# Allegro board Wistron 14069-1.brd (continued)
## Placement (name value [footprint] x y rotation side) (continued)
R1619  10KR2J-3-GP  [R402H16]  170.02 54.83 90 top
R1620  10KR2J-3-GP  [R402H16]  168.81 50.16 90 top
R1621  10KR2J-3-GP  [R402H16]  170.94 48.56 90 top
R1622  10KR2J-3-GP  [R402H16]  172.01 46.46 270 top
R1701  0R2J-2-GP  [R402H16]  130.16 43.31 90 top
R1703  0R0402-PAD-2-GP  [0R0402-PAD-1]  180.52 39.75 90 top
R1704  560R2J-3-GP  [R402H16]  130.86 45.82 270 top
R1705  30R2J-1-GP  [R402H16]  130.84 44.73 270 top
R1706  1KR2J-1-GP  [R402H16]  132.56 42.94 0 top
R1707  1KR2J-1-GP  [R402H16]  124.53 41.22 270 top
R1708  0R2J-2-GP  [R402H16]  221.79 9.73 270 top
R1709  0R2J-2-GP  [R402H16]  196.63 27.64 270 top
R1710  0R2J-2-GP  [R402H16]  196.63 28.79 270 top
R1711  0R2J-2-GP  [R402H16]  221.82 8.64 270 top
R1801  0R0402-PAD-2-GP  [0R0402-PAD-1]  177.23 30.65 270 top
R1803  2K7R2F-GP  [R402H16]  138.13 57.98 0 top
R1807  1MR2J-1-GP  [R402H16]  138.13 60.25 0 top
R1808  10MR3J-L1-GP  [R603H22]  146.25 33.32 90 top
R1809  10KR2J-3-GP  [R402H16]  153.56 31.63 0 top
R1810  10KR2J-3-GP  [R402H16]  165.97 28.66 0 top
R1811  10KR2J-3-GP  [R402H16]  154.66 31.61 0 top
R1812  10KR2J-3-GP  [R402H16]  178.74 31.09 180 top
R1814  10KR2J-3-GP  [R402H16]  152.54 31.78 0 top
R1815  10KR2J-3-GP  [R402H16]  167 28.66 0 top
R1901  10KR2J-3-GP  [R402H16]  152.04 26.08 90 top
R1902  10KR2J-3-GP  [R402H16]  148.98 28.98 0 top
R1905  10KR2J-3-GP  [R402H16]  152.37 27.56 0 top
R1907  10KR2J-3-GP  [R402H16]  147.96 29.53 0 top
R1908  10KR2J-3-GP  [R402H16]  134.77 27.15 0 top
R1909  22R2J-2-GP  [R402H16]  162.56 24.36 0 top
R1910  22R2J-2-GP  [R402H16]  164.03 24.09 90 top
R1911  22R2J-2-GP  [R402H16]  161.52 24.36 0 top
R2002  1KR2F-3-GP  [R402H16]  170.3 37.49 90 top
R2003  1KR2F-3-GP  [R402H16]  170.25 38.54 90 top
R2004  1KR2F-3-GP  [R402H16]  176.75 36.23 180 top
R2005  1KR2F-3-GP  [R402H16]  176.79 32.65 180 top
R2006  75R3J-L-GP  [R603H22]  238.27 106.75 180 top
R2007  0R0402-PAD-2-GP  [0R0402-PAD-1]  149.91 23.91 90 top
R2008  2K2R2J-2-GP  [R402H16]  236.66 100.3 0 top
R2009  75R3J-L-GP  [R603H22]  237.03 106.75 180 top
R2010  1KR2J-1-GP  [R402H16]  238.13 100.72 90 top
R2011  10KR2J-3-GP  [R402H16]  132.81 32.19 180 top
R2012  0R2J-2-GP  [R402H16]  128.96 33.91 90 top
R2014  0R0402-PAD-2-GP  [0R0402-PAD-1]  127.99 28.35 270 top
R2015  2K2R2J-2-GP  [R402H16]  132.35 33.75 90 top
R2016  499R2F-2-GP  [R402H16]  166.73 37.71 90 top
R2017  33R2J-2-GP  [R402H16]  140.87 33.42 180 top
R2018  499R2F-2-GP  [R402H16]  167.45 35.23 90 top
R2019  1KR2J-1-GP  [R402H16]  166.69 40.13 90 top
R2020  33R2J-2-GP  [R402H16]  136.19 37.63 90 top
R2021  1KR2J-1-GP  [R402H16]  168.24 30.63 90 top
R2022  33R2J-2-GP  [R402H16]  139.41 33.86 90 top
R2023  10KR2J-3-GP  [R402H16]  158.97 29.53 0 top
R2024  8K2R2J-3-GP  [R402H16]  157.51 29.76 90 top
R2025  33R2J-2-GP  [R402H16]  136.73 32.77 270 top
R2026  10KR2J-3-GP  [R402H16]  146.36 42.48 90 bottom
R2027  10KR2J-3-GP  [R402H16]  130.05 27.84 0 top
R2028  33R2J-2-GP  [R402H16]  130.18 41.02 90 top
R2029  33R2J-2-GP  [R402H16]  130.17 39.99 90 top
R2030  1KR2J-1-GP  [R402H16]  149.17 27.09 0 top
R2031  100KR2J-1-GP  [R402H16]  131.09 28.83 0 top
R2032  10KR2J-3-GP  [R402H16]  150.21 26.55 0 top
R2034  10KR2J-3-GP  [R402H16]  149.11 31.95 0 top
R2035  1KR2J-1-GP  [R402H16]  124.54 36.8 270 top
R2036  0R2J-2-GP  [R402H16]  127.03 36.16 90 top
R2037  51D1R2F-GP  [R402H16]  130.54 38.39 270 top
R2038  51R2F-2-GP  [R402H16]  124.49 40.18 270 top
R2040  51R2F-2-GP  [R402H16]  124.48 39.12 270 top
R2043  51R2F-2-GP  [R402H16]  124.54 37.94 270 top
R2045  10KR2J-3-GP  [R402H16]  156.1 26.76 0 top
R2046  20KR2J-L2-GP  [R402H16]  143.18 25.28 90 top
R2047  10KR2J-3-GP  [R402H16]  148.11 26.97 0 top
R2048  1KR2J-1-GP  [R402H16]  154.06 28.92 0 top
R2049  20KR2J-L2-GP  [R402H16]  182.68 8.48 270 top
R2053  470R2F-GP  [R402H16]  152.26 23.45 180 top
R2054  4K7R2J-2-GP  [R402H16]  182.45 5.82 90 top
R2056  20KR2F-L-GP  [R402H16]  196.09 13.7 270 top
R2057  0R0402-PAD-2-GP  [0R0402-PAD-1]  196.1 12.61 90 top
R2058  1KR2J-1-GP  [R402H16]  195.53 14.98 270 top
R2059  1KR2J-1-GP  [R402H16]  195.88 21.51 0 top
R2060  0R0402-PAD-2-GP  [0R0402-PAD-1]  194.84 21.51 0 top
R2066  10KR2J-3-GP  [R402H16]  154.57 26.15 90 top
R2067  0R0402-PAD-2-GP  [0R0402-PAD-1]  130.68 31.11 180 top
R2101  0R2J-2-GP  [R402H16]  155.17 28.92 180 top
R2102  0R0603-PAD-2-GP-U  [0R0603-PAD-1-U]  162.31 27.69 0 top
R2104  0R0603-PAD-2-GP-U  [0R0603-PAD-1-U]  152.6 44.35 270 bottom
R2105  0R0603-PAD-2-GP-U  [0R0603-PAD-1-U]  135.71 35.53 270 top
R2106  30R2J-1-GP  [R402H16]  135.18 41.6 270 top
R2107  0R0402-PAD-2-GP  [0R0402-PAD-1]  142.9 50.38 270 bottom
R2108  0R0603-PAD-2-GP-U  [0R0603-PAD-1-U]  142.75 32.89 90 top
R2109  0R0603-PAD-2-GP-U  [0R0603-PAD-1-U]  165.14 36.75 270 bottom
R2110  0R0402-PAD-2-GP  [0R0402-PAD-1]  140.19 50.38 90 bottom
R2129  0R0603-PAD-2-GP-U  [0R0603-PAD-1-U]  167.08 36.53 270 top
R2130  30R2J-1-GP  [R402H16]  132.06 41.32 270 top
R2201  10KR2J-3-GP  [R402H16]  167.66 48.19 270 top
R2202  1KR2J-1-GP  [R402H16]  164.03 31.69 270 top
R2203  4K7R2J-2-GP  [R402H16]  162.15 31.53 90 top
R2204  20KR2J-L2-GP  [R402H16]  164.04 32.78 270 top
R2205  4K7R2J-2-GP  [R402H16]  162.15 32.62 90 top
R2206  20KR2J-L2-GP  [R402H16]  164.05 30.61 270 top
R2207  4K7R2J-2-GP  [R402H16]  162.15 30.46 90 top
R2208  20KR2J-L2-GP  [R402H16]  164.04 33.86 270 top
R2209  1KR2J-1-GP  [R402H16]  162.16 33.7 90 top
R2210  4K7R2J-2-GP  [R402H16]  158.77 32.59 270 top
R2211  20KR2J-L2-GP  [R402H16]  156.89 32.59 90 top
R2212  4K7R2J-2-GP  [R402H16]  158.76 33.72 270 top
R2213  1KR2J-1-GP  [R402H16]  156.88 33.72 90 top
R2214  4K7R2J-2-GP  [R402H16]  170.96 27.75 180 top
R2215  20KR2J-L2-GP  [R402H16]  170.53 29.73 270 top
R2217  4K7R2J-2-GP  [R402H16]  164.6 28.08 180 top
R2218  20KR2J-L2-GP  [R402H16]  163.51 28.08 180 top
R2219  4K7R2J-2-GP  [R402H16]  168.27 27.45 180 top
R2220  20KR2J-L2-GP  [R402H16]  169.33 27.44 180 top
R2221  4K7R2J-2-GP  [R402H16]  160.04 28.03 180 top
R2222  20KR2J-L2-GP  [R402H16]  161.09 28.08 180 top
R2223  4K7R2J-2-GP  [R402H16]  169.99 34.65 0 top
R2224  20KR2J-L2-GP  [R402H16]  168.91 34.65 0 top
R2225  10KR2J-3-GP  [R402H16]  167.68 47.13 270 top
R2227  1K5R2J-3-GP  [R402H16]  135.18 42.62 90 top
R2301  0R0603-PAD-2-GP-U  [0R0603-PAD-1-U]  145.42 52.38 90 bottom
R2302  0R0603-PAD-2-GP-U  [0R0603-PAD-1-U]  170.81 63.37 270 top
R2303  0R0603-PAD-2-GP-U  [0R0603-PAD-1-U]  149.82 44.5 90 bottom
R2304  0R0603-PAD-2-GP-U  [0R0603-PAD-1-U]  159.25 23.51 270 top
R2406  0R0603-PAD-2-GP-U  [0R0603-PAD-1-U]  20.45 76.58 270 top
R2475  43D2R2F-GP  [R402H16]  210.97 64.81 0 top
R2476  0R2J-2-GP  [R402H16]  207.7 62.89 90 top
R2477  0R2J-2-GP  [R402H16]  208.46 63.94 90 top
R2478  0R2J-2-GP  [R402H16]  226.8 75.36 0 top
R2479  1KR2J-1-GP  [R402H16]  213.36 52.94 0 top
R2480  0R0402-PAD-2-GP  [0R0402-PAD-1]  237.08 40.18 0 top
R2502  1KR2J-1-GP  [R402H16]  175.06 24.23 90 top
R2503  1KR2J-1-GP  [R402H16]  188.92 25.92 270 top
R2504  1KR2J-1-GP  [R402H16]  173.99 12.57 90 top
R2505  15R2F-2-GP  [R402H16]  175.01 25.5 90 top
R2506  15R2F-2-GP  [R402H16]  188.92 24.9 90 top
R2507  15R2F-2-GP  [R402H16]  175.06 23.16 90 top
R2508  15R2F-2-GP  [R402H16]  188.95 22.86 90 top
R2509  10KR2F-2-GP  [R402H16]  180.44 13.28 270 top
R2510  15R2F-2-GP  [R402H16]  188.95 20.83 90 top
R2511  0R2J-2-GP  [R402H16]  176.83 12.4 270 top
R2512  0R2J-2-GP  [R402H16]  180.06 5.92 90 top
R2514  1K5R2F-2-GP  [R402H16]  100.58 20.19 90 top
R2515  1KR2J-1-GP  [R402H16]  101.27 18.52 0 top
R2516  45K3R2F-L-GP  [R402H16]  103.5 21.84 90 top
R2601  0R0402-PAD-2-GP  [0R0402-PAD-1]  214.71 233.4 90 top
R2602  4K7R2J-2-GP  [R402H16]  148.97 232.41 270 top
R2603  20KR2J-L2-GP  [R402H16]  148.97 231.39 90 top
R2604  0R0402-PAD-2-GP  [0R0402-PAD-1]  151.76 231.39 0 top
R2605  2K2R2J-2-GP  [R402H16]  142.6 232.39 90 top
R2606  8K2R2F-1-GP  [R402H16]  150.62 231.39 0 top
R2607  100R2F-L1-GP-U  [R402H14]  142.59 231.28 90 top
R2608  10KR2J-3-GP  [R402H16]  216.07 227.84 90 top
R2609  0R0603-PAD-2-GP-U  [0R0603-PAD-1-U]  224.49 231.39 0 top
R2610  2K2R2J-2-GP  [R402H16]  211.49 236.38 90 top
R2611  4K7R2J-2-GP  [R402H16]  216.07 228.87 270 top
R2612  4K7R2J-2-GP  [R402H16]  217.52 228.3 180 top
R2613  100R2J-2-GP  [R402H14]  215.93 225.2 270 top
R2614  10KR2J-3-GP  [R402H16]  215.93 226.34 270 top
R2615  100KR2J-1-GP  [R402H16]  218.62 225.38 0 top
R2616  2K2R2J-2-GP  [R402H16]  224.67 226.9 180 top
R2617  330R2F-GP  [R402H16]  223.54 226.89 180 top
R2618  4K7R2J-2-GP  [R402H16]  213.01 235.49 180 top
R2619  20KR2J-L2-GP  [R402H16]  214.03 235.92 180 top
R2620  8K2R2J-3-GP  [R402H16]  214.71 234.43 90 top
R2621  0R0603-PAD-2-GP-U  [0R0603-PAD-1-U]  236.1 147.68 0 top
R2622  4K7R2J-2-GP  [R402H16]  236.05 152.01 0 top
R2623  20KR2J-L2-GP  [R402H16]  236.57 150.1 180 top
R2624  330R2F-GP  [R402H16]  233.12 36.65 180 top
R2625  10KR2J-3-GP  [R402H16]  234.71 45.76 0 top
R2626  2K2R2J-2-GP  [R402H16]  236.09 36.96 90 top
R2627  100KR2J-1-GP  [R402H16]  231.37 47.02 270 top
R2628  0R0402-PAD-2-GP  [0R0402-PAD-1]  236.42 135.39 0 top
R2629  10KR2J-3-GP  [R402H16]  233.25 47.02 90 top
R2630  4K7R2J-2-GP  [R402H16]  234.7 43.87 0 top
R2631  8K2R2J-3-GP  [R402H16]  235.32 136.33 180 top
R2632  4K7R2J-2-GP  [R402H16]  238.42 41.88 180 top
R2633  2K2R2J-2-GP  [R402H16]  233.11 34.72 180 top
R2634  100R2J-2-GP  [R402H14]  231.84 39.66 0 top
R2701  0R0603-PAD-2-GP-U  [0R0603-PAD-1-U]  21.84 64.65 270 top
R2705  0R0603-PAD-2-GP-U  [0R0603-PAD-1-U]  8.06 15.05 90 top
R2706  0R0603-PAD-2-GP-U  [0R0603-PAD-1-U]  40.37 11.89 0 top
R2707  0R0603-PAD-2-GP-U  [0R0603-PAD-1-U]  6.36 55.74 90 top
R2708  10KR2J-3-GP  [R402H16]  25.66 35.76 180 top
R2709  1KR2J-1-GP  [R402H16]  24.63 50.8 270 top
R2710  1KR2J-1-GP  [R402H16]  30.49 39.44 0 top
R2711  10KR2J-3-GP  [R402H16]  33.3 35.2 0 top
R2712  220KR2J-L2-GP  [R402H16]  27.16 36.22 90 top
R2713  1KR2J-1-GP  [R402H16]  29.38 39.44 0 top
R2714  33R2J-2-GP  [R402H16]  24.49 48.7 90 top
R2715  10KR2J-3-GP  [R402H16]  8.93 45.59 270 top
R2716  20KR2F-L-GP  [R402H16]  15.72 40.84 0 top
R2907  39K2R2F-L-GP  [R402H16]  9.18 44.12 0 top
R2908  0R2J-2-GP  [R402H16]  7.1 44.12 0 top
R2909  20KR2F-L-GP  [R402H16]  8.14 44.12 0 top
R2920  20KR2F-L-GP  [R402H16]  47.22 9.32 90 top
R2921  0R0402-PAD-2-GP  [0R0402-PAD-1]  31.05 13.72 0 top
R2922  0R0402-PAD-2-GP  [0R0402-PAD-1]  32.07 13.72 0 top
R2926  20KR2F-L-GP  [R402H16]  44.79 5.97 0 top
R2930  1KR2J-1-GP  [R402H16]  156.44 18.77 90 top
R2931  10KR2J-3-GP  [R402H16]  37.44 11.66 180 top
R2932  4K7R2J-2-GP  [R402H16]  14.07 15 0 top
R2934  0R0402-PAD-2-GP  [0R0402-PAD-1]  39.31 10.04 90 top
R2935  10KR2J-3-GP  [R402H16]  158.35 19.89 90 top
R2936  0R0402-PAD-2-GP  [0R0402-PAD-1]  14.12 8.1 90 top
R2937  1KR2J-1-GP  [R402H16]  154.86 19.3 180 top
R2938  1KR2J-1-GP  [R402H16]  156.44 19.91 90 top
R2939  1KR2J-1-GP  [R402H16]  155.32 20.96 270 top
R2940  1KR2J-1-GP  [R402H16]  114.38 7.47 0 top
R2941  4K7R2J-2-GP  [R402H16]  12.93 15 0 top
R2942  4K7R2J-2-GP  [R402H16]  26.98 16.1 0 top
R2943  22KR2J-GP  [R402H16]  22.8 16.97 90 top
R2944  4K7R2J-2-GP  [R402H16]  25.83 16.1 0 top
R2945  75R2J-1-GP  [R402H16]  22.36 18.52 0 top
R2946  22KR2J-GP  [R402H16]  20.89 16.97 270 top
R2947  75R2J-1-GP  [R402H16]  21.32 18.52 0 top
R2948  1KR2J-1-GP  [R402H16]  17.46 16 0 top
R2949  1KR2J-1-GP  [R402H16]  18.86 16 0 top
R2950  1KR2J-1-GP  [R402H16]  13.18 9.77 180 top
R2951  1KR2J-1-GP  [R402H16]  14.32 9.77 180 top
R2952  1KR2J-1-GP  [R402H16]  27.25 11.05 180 top
R2953  1KR2J-1-GP  [R402H16]  26.1 11.05 180 top
R2954  1KR2J-1-GP  [R402H16]  114.38 5.56 180 top
R2955  1KR2J-1-GP  [R402H16]  82.3 5.97 90 top
R3001  10KR2F-2-GP  [R402H16]  20.88 55.7 0 top
R3002  75R2J-1-GP  [R402H16]  19.18 64.36 180 top
R3003  75R2J-1-GP  [R402H16]  17.81 64.36 180 top
R3004  75R2J-1-GP  [R402H16]  13.17 63.09 180 top
R3005  75R2J-1-GP  [R402H16]  12.16 63.09 180 top
R3006  22KR2J-GP  [R402H16]  11.14 63.09 0 top
R3007  22KR2J-GP  [R402H16]  14.19 63.09 0 top
R3008  2K2R2J-2-GP  [R402H16]  8.57 62.98 180 top
R3009  75R2J-1-GP  [R402H16]  7.56 62.98 180 top
R3010  75R2J-1-GP  [R402H16]  6.54 62.98 180 top
R3011  2K2R2J-2-GP  [R402H16]  5.52 62.98 180 top
R3012  5K1R2F-2-GP  [R402H16]  19.76 54.71 0 top
R3013  20KR2F-L-GP  [R402H16]  18.7 54.71 0 top
R3014  1KR2J-1-GP  [R402H16]  18.03 59.09 180 top
R3015  1KR2J-1-GP  [R402H16]  19.18 59.09 180 top
R3016  1KR2J-1-GP  [R402H16]  11.83 57.82 180 top
R3017  1KR2J-1-GP  [R402H16]  12.97 57.82 180 top
R3018  1KR2J-1-GP  [R402H16]  6.56 57.69 180 top
R3019  1KR2J-1-GP  [R402H16]  7.7 57.69 180 top
R3101  0R0402-PAD-2-GP  [0R0402-PAD-1]  35.56 89.48 90 top
R3102  2K49R2F-GP  [R402H16]  24.01 89.56 0 top
R3103  0R3J-0-U-GP  [R603H22]  31.53 94.35 90 top
R3104  0R2J-2-GP  [R402H16]  33.1 84.98 0 top
R3107  0R0402-PAD-2-GP  [0R0402-PAD-1]  30.55 81.26 90 top
R3108  0R0402-PAD-2-GP  [0R0402-PAD-1]  25.54 78.82 270 top
R3109  680R2F-GP  [R402H16]  25.66 91.74 0 top
R3110  0R2J-2-GP  [R402H16]  33.6 49.59 0 top
R3111  10MR2J-L-GP  [R402H16]  26.68 91.74 180 top
R3112  0R2J-2-GP  [R402H16]  80.37 45.9 0 top
R3113  2KR2F-3-GP  [R402H16]  35.83 83.16 180 top
R3114  8K2R2J-3-GP  [R402H16]  36.09 80.48 90 top
R3115  1KR2J-1-GP  [R402H16]  32.04 83.94 0 top
R3118  15KR2J-1-GP  [R402H16]  30.53 83.23 270 top
R3120  1KR2J-1-GP  [R402H16]  34.16 82.64 270 top
R3158  47KR2J-2-GP  [R402H16]  35.24 100.57 270 top
R3159  100KR2J-1-GP  [R402H16]  38.91 95.11 180 top
R3160  10KR2J-3-GP  [R402H16]  37.85 95.13 180 top
R3161  1KR2J-1-GP  [R402H16]  36 102.92 180 top
R3162  10KR2J-3-GP  [R402H16]  34.95 102.91 0 top
R3163  390KR2J-GP  [R402H16]  36.82 95.14 180 top
R3164  0R0805-PAD-2-GP-U  [0R0805-PAD-1-U]  31.66 97.61 0 top
R3165  10KR2J-3-GP  [R402H16]  25.54 79.97 90 top
R3166  10KR2J-3-GP  [R402H16]  35.57 88.43 90 top
R3167  10KR2J-3-GP  [R402H16]  76.07 49.66 270 top
R3168  1KR2J-1-GP  [R402H16]  76.07 48.51 90 top
R3204  330R3J-L-GP  [R603H22]  30.14 102.03 0 top
R3205  330R3J-L-GP  [R603H22]  28.87 102.03 0 top
R3206  330R3J-L-GP  [R603H22]  29.59 122.94 90 top
R3401  0R2J-2-GP  [R402H16]  69.64 27.26 180 top
R3402  10KR2J-3-GP  [R402H16]  71.53 21.25 90 top
R3403  10KR2J-3-GP  [R402H16]  73.43 23.54 90 top
R3405  10KR2J-3-GP  [R402H16]  70.66 27.26 180 top
R3406  10KR2J-3-GP  [R402H16]  76.15 25.1 270 top
R3407  10KR2J-3-GP  [R402H16]  76.57 23.63 0 top
R3408  0R2J-2-GP  [R402H16]  73.43 21.25 270 top
R3409  0R2J-2-GP  [R402H16]  73.43 22.39 90 top
R3410  0R2J-2-GP  [R402H16]  71.83 27.23 180 top
R3411  0R2J-2-GP  [R402H16]  75.52 23.63 180 top
R3412  0R2J-2-GP  [R402H16]  79.3 28.29 270 top
R3413  0R2J-2-GP  [R402H16]  79.3 27.27 270 top
R3415  20KR2F-L-GP  [R402H16]  73.76 32.83 180 top
R3416  10KR2J-3-GP  [R402H16]  73.43 24.68 90 top
R3417  46K4R2F-2-GP  [R402H16]  74.78 32.83 180 top
R3418  0R2J-2-GP  [R402H16]  73.53 46.35 0 top
R3501  1KR2J-1-GP  [R402H16]  214.33 94.24 90 top
R3502  10KR2F-2-GP  [R402H16]  218.65 92.58 0 top
R3514  0R3J-0-U-GP  [R603H22]  186.41 79.32 0 top
R3515  0R3J-0-U-GP  [R603H22]  185.24 79.32 0 top
R3516  100KR2J-1-GP  [R402H16]  216.92 93.4 0 top
R3519  0R3J-0-U-GP  [R603H22]  221.73 107.32 0 top
R3520  0R3J-0-U-GP  [R603H22]  223 107.32 0 top
R3521  100KR2J-1-GP  [R402H16]  222.54 92.52 180 top
R3522  10KR2J-3-GP  [R402H16]  224.64 89.22 0 top
R3523  2K7R2J-GP  [R402H16]  224.19 92.63 90 top
R3524  10KR2J-3-GP  [R402H16]  224.64 91.15 180 top
R3525  10KR2F-2-GP  [R402H16]  214.3 90.78 90 top
R3526  10KR2F-2-GP  [R402H16]  210.52 94.82 270 top
R3527  10KR2J-3-GP  [R402H16]  216.08 90.22 180 top
R3601  10KR2J-3-GP  [R402H16]  30.73 124.69 0 top
R3604  15KR2F-GP  [R402H16]  28.71 124.67 180 top
R3701  10KR2J-3-GP  [R402H16]  97.63 9.2 270 top
R3702  15KR2F-GP  [R402H16]  96.11 9.64 180 top
R3703  10KR2J-3-GP  [R402H16]  84.71 9.66 270 top
R3704  15KR2F-GP  [R402H16]  83.18 9.15 0 top
R3705  10KR2J-3-GP  [R402H16]  117.22 18.54 90 top
R3706  15KR2F-GP  [R402H16]  118.94 18 0 top
R3813  10KR2J-3-GP  [R402H16]  14.6 179.89 180 top
R3814  10KR2J-3-GP  [R402H16]  11.64 179.92 180 top
R3815  0R0402-PAD-2-GP  [0R0402-PAD-1]  15.64 179.89 180 top
R3816  15KR2F-GP  [R402H16]  15.54 181.85 180 top
R3821  10KR2J-3-GP  [R402H16]  5.82 182.78 90 top
R3822  10KR2J-3-GP  [R402H16]  93.24 16.38 180 top
R3914  10KR2J-3-GP  [R402H16]  125.73 19.44 180 top
R3916  10KR2J-3-GP  [R402H16]  124.58 19.44 180 top
R3917  0R3J-0-U-GP  [R603H22]  156.43 11.07 180 top
R3918  0R0402-PAD-2-GP  [0R0402-PAD-1]  123.51 21.42 0 top
R3919  15KR2F-GP  [R402H16]  125.03 21.84 90 top
R3920  0R0402-PAD-2-GP  [0R0402-PAD-1]  156.45 8.39 180 top
R4010  0R2J-2-GP  [R402H16]  236.83 229.3 180 top
R4011  0R2J-2-GP  [R402H16]  234.6 226.06 180 top
R4014  0R2J-2-GP  [R402H16]  235.85 226.05 180 top
R4015  0R2J-2-GP  [R402H16]  232.27 224.01 0 top
R4016  0R2J-2-GP  [R402H16]  236.75 220.47 90 top
R4017  0R2J-2-GP  [R402H16]  238.47 223.54 0 top
R4018  47KR2F-GP  [R402H16]  235.34 230.38 270 top
R4019  0R2J-2-GP  [R402H16]  235.35 229.35 90 top
R4020  20KR2F-L-GP  [R402H16]  235.35 228.33 90 top
R4021  0R2J-2-GP  [R402H16]  221.58 111.25 0 bottom
R4022  0R2J-2-GP  [R402H16]  220.52 111.28 180 bottom
R4023  0R2J-2-GP  [R402H16]  219.2 111.3 0 bottom
R4024  0R2J-2-GP  [R402H16]  238.56 218.69 180 top
R4025  0R0402-PAD-2-GP  [0R0402-PAD-1]  233.32 217.81 270 top
R4026  0R2J-2-GP  [R402H16]  233.76 219.28 0 top
R4202  0R0402-PAD-2-GP  [0R0402-PAD-1]  186.56 84.86 180 top
R4203  0R0402-PAD-2-GP  [0R0402-PAD-1]  189.99 84.81 180 top
R4303  22KR2F-GP  [R402H16]  234.09 179.86 0 top
R4305  0R0402-PAD-2-GP  [0R0402-PAD-1]  234.09 177.9 180 top
R4306  10KR2J-3-GP  [R402H16]  218.2 193.14 90 top
R4308  220R5J-GP  [R805H24]  214.52 193.1 270 top
R4309  220R5J-GP  [R805H24]  214.56 198.8 270 top
R4310  220R5J-GP  [R805H24]  214.42 204.52 270 top
R4311  10KR2J-3-GP  [R402H16]  215.47 184.4 270 top
R4606  10KR2F-2-GP  [R402H16]  72.09 216.92 0 top
R4693  10KR2J-3-GP  [R402H16]  60.58 225.2 270 top
R5201  10KR2J-3-GP  [R402H16]  55.64 98.44 0 top
R5204  1KR2J-1-GP  [R402H16]  56.56 94.82 180 top
R5205  10KR2J-3-GP  [R402H16]  54.16 95.71 90 top
R5601  100KR2F-L1-GP  [R402H16]  20.22 234.96 180 top
R5602  470R2J-2-GP  [R402H16]  22.94 214.22 90 top
R5603  470R2J-2-GP  [R402H16]  22.94 217.81 90 top
R5604  470R2J-2-GP  [R402H16]  22.94 219 90 top
R5605  470R2J-2-GP  [R402H16]  22.94 211.84 90 top
R5606  470R2J-2-GP  [R402H16]  22.94 213.03 90 top
R5607  470R2J-2-GP  [R402H16]  22.94 215.42 90 top
R5608  470R2J-2-GP  [R402H16]  22.94 216.61 90 top
R5609  470R2J-2-GP  [R402H16]  22.94 220.19 90 top
R5610  2K2R2J-2-GP  [R402H16]  23.72 224.43 0 top
R5611  2K2R2J-2-GP  [R402H16]  23.68 222.49 180 top
R5612  2K2R2J-2-GP  [R402H16]  19.12 222.6 180 top
R5613  2K2R2J-2-GP  [R402H16]  19.17 224.55 0 top
R5614  1MR2J-1-GP  [R402H16]  20.73 230.84 90 top
R5615  20KR2F-L-GP  [R402H16]  18.21 226.46 0 top
R5701  100KR2J-1-GP  [R402H16]  17.49 203.18 270 top
R5702  20KR2J-L2-GP  [R402H16]  26.18 197.26 0 top
R5703  1KR2J-1-GP  [R402H16]  18.73 197.69 270 top
R5704  10KR2J-3-GP  [R402H16]  24.59 197.83 270 top
R5705  15KR2F-GP  [R402H16]  25.12 196.29 0 top
R5706  100KR2J-1-GP  [R402H16]  14.57 201.53 180 top
R5707  4K7R2J-2-GP  [R402H16]  18.73 196.55 90 top
R5708  1MR2J-1-GP  [R402H16]  18.73 195.53 90 top
R5709  4K99R2F-L-GP  [R402H16]  25.15 194.31 0 top
R5710  1MR2J-1-GP  [R402H16]  18.73 194.52 90 top
R5711  2K2R2J-2-GP  [R402H16]  20.76 209.82 0 top
R5712  100KR2J-1-GP  [R402H16]  22.27 204.24 180 top
R5713  2K2R2J-2-GP  [R402H16]  22.6 209.77 0 top
R5714  100KR2J-1-GP  [R402H16]  21.22 204.24 0 top
R6102  0R2J-2-GP  [R402H16]  149.31 97.32 90 top
R6103  0R2J-2-GP  [R402H16]  149.31 98.46 90 top
R6104  0R2J-2-GP  [R402H16]  149.31 99.61 90 top
R6105  10KR2J-3-GP  [R402H16]  162.39 91.36 90 top
R6106  0R0402-PAD-2-GP  [0R0402-PAD-1]  162.31 94.1 270 top
R6107  0R0402-PAD-2-GP  [0R0402-PAD-1]  162.14 95.12 270 top
R6108  33R2J-2-GP  [R402H16]  149.31 96.18 90 top
R6109  0R0402-PAD-2-GP  [0R0402-PAD-1]  149.31 95.04 270 top
R6110  10KR2J-3-GP  [R402H16]  162.4 90.32 90 top
R6114  0R2J-2-GP  [R402H16]  148.8 90.39 90 top
R6115  0R2J-2-GP  [R402H16]  148.8 91.53 90 top
R6116  0R2J-2-GP  [R402H16]  162.24 92.39 270 top
R6117  0R2J-2-GP  [R402H16]  162.35 89.27 270 top
R6118  0R2J-2-GP  [R402H16]  149.3 88.47 90 top
R6209  0R0402-PAD-2-GP  [0R0402-PAD-1]  112.2 52.05 90 top
R6210  0R2J-2-GP  [R402H16]  197.55 26.5 270 top
R6211  0R0402-PAD-2-GP  [0R0402-PAD-1]  98.7 53.52 270 top
R6212  0R0402-PAD-2-GP  [0R0402-PAD-1]  96.44 54.61 0 top
R6213  0R0402-PAD-2-GP  [0R0402-PAD-1]  96.44 56.54 0 top
R6214  33R2J-2-GP  [R402H16]  96.48 51.77 0 top
R6215  0R0402-PAD-2-GP  [0R0402-PAD-1]  96.44 58.46 0 top
R6402  68R3J-GP  [R603H22]  215.75 10.41 270 top
R6403  10KR2J-3-GP  [R402H16]  211.35 12.42 90 top
R6404  33R2J-2-GP  [R402H16]  211.35 11.4 270 top
R6405  10KR2J-3-GP  [R402H16]  210.16 17.22 90 top
R6406  22KR2J-GP  [R402H16]  202.51 22.73 0 top
R6407  22KR2J-GP  [R402H16]  200.08 17.48 90 top
R6408  4K7R2J-2-GP  [R402H16]  201.47 22.73 0 top
R6409  10KR2J-3-GP  [R402H16]  206.88 17.17 0 top
R6410  75R5J-GP  [R805H24]  198.15 18.64 0 top
R6411  10KR2J-3-GP  [R402H16]  213.41 10.64 270 top
R6412  22KR2J-GP  [R402H16]  178.56 14.25 90 top
R6413  22KR2J-GP  [R402H16]  177.42 19.18 90 top
R6414  4K7R2J-2-GP  [R402H16]  179.58 19.18 270 top
R6415  75R5J-GP  [R805H24]  185.49 14.75 270 top
R6416  4K7R2J-2-GP  [R402H16]  183.01 18.97 270 top
R6417  75R5J-GP  [R805H24]  188.24 13.94 0 top
R6418  33R2J-2-GP  [R402H16]  232.89 19.57 270 top
R6419  10KR2J-3-GP  [R402H16]  232.89 18.43 90 top
R6420  4K7R2J-2-GP  [R402H16]  234.09 31.67 0 top
R6421  4K7R2J-2-GP  [R402H16]  231.39 33.89 90 top
R6424  165R3F-GP  [R603H22]  239.29 34.16 0 top
R6426  75R3F-GP  [R603H22]  232.44 23.29 90 top
R6427  75R3F-GP  [R603H22]  232.46 25.43 90 top
R6801  10KR2J-3-GP  [R402H16]  231.5 110.18 270 top
R6821  22KR2J-GP  [R402H16]  207.65 13.87 90 top
R6822  22KR2J-GP  [R402H16]  206.12 11.71 0 top
R6823  4K7R2J-2-GP  [R402H16]  207.65 14.88 270 top
R6824  220R5J-GP  [R805H24]  200.94 11.35 180 top
R6825  220R5J-GP  [R805H24]  203.68 11.71 270 top
R7919  4K7R2J-2-GP  [R402H16]  221.88 47.07 270 top
R7922  33R2J-2-GP  [R402H16]  220.34 75.72 0 top
R7924  33R2J-2-GP  [R402H16]  219.3 75.72 0 top
R7925  0R0402-PAD-2-GP  [0R0402-PAD-1]  214.82 52.48 270 top
R7928  1KR2J-1-GP  [R402H16]  216.35 77.75 90 top
R7929  0R0402-PAD-2-GP  [0R0402-PAD-1]  219.94 77.4 90 top
R7938  100KR2J-1-GP  [R402H16]  212.42 67.22 0 top
R7939  33R2J-2-GP  [R402H16]  208.53 69.37 270 top
R7943  20KR2J-L2-GP  [R402H16]  220.45 78.85 180 top
R7946  10KR2F-2-GP  [R402H16]  235.34 50.93 180 top
R7947  1KR2J-1-GP  [R402H16]  208.86 76.25 180 top
R7948  1KR2J-1-GP  [R402H16]  209.49 73.74 90 top
R7949  1KR2J-1-GP  [R402H16]  209.51 72.56 90 top
R7950  1KR2J-1-GP  [R402H16]  229.46 52.15 0 top
R7951  33R2J-2-GP  [R402H16]  223.55 75.74 180 top
R7952  56KR2F-GP  [R402H16]  232.41 49.65 0 top
R7953  10KR2F-2-GP  [R402H16]  233.15 52.04 0 top
R7954  0R0402-PAD-2-GP  [0R0402-PAD-1]  223.77 50.16 0 top
R7958  6K49R2F-1-GP  [R402H16]  231.16 52.87 270 top
R7959  10KR2F-2-GP  [R402H16]  230.93 50.16 270 top
R7961  10KR2J-3-GP  [R402H16]  227.69 78.77 180 top
R7963  17K8R2F-GP  [R402H16]  224.89 47.68 0 top
R7964  10KR2F-2-GP  [R402H16]  225.91 47.68 0 top
R7965  1KR2J-1-GP  [R402H16]  199.66 76.01 270 top
R7966  1KR2J-1-GP  [R402H16]  199.64 74.96 270 top
R7967  1KR2J-1-GP  [R402H16]  199.62 73.84 270 top
R7968  17K8R2F-GP  [R402H16]  229.84 47.68 0 top
R7969  10KR2F-2-GP  [R402H16]  228.83 47.68 0 top
R7974  0R0402-PAD-2-GP  [0R0402-PAD-1]  226.67 78.76 180 top
R7975  0R0402-PAD-2-GP  [0R0402-PAD-1]  213.87 49 270 top
R7976  0R0402-PAD-2-GP  [0R0402-PAD-1]  221.88 45.75 90 top
R7977  0R2J-2-GP  [R402H16]  221.89 43.87 90 top
R7997  10KR2F-2-GP  [R402H16]  226.16 49.15 90 top
R7998  10KR2F-2-GP  [R402H16]  227.4 52.58 0 top
R8000  10KR2J-3-GP  [R402H16]  230.82 75.32 180 top
R8001  10KR2J-3-GP  [R402H16]  222.5 74.83 180 top
R8013  10KR2J-3-GP  [R402H16]  222.12 50.86 0 top
R8014  10KR2J-3-GP  [R402H16]  221.07 50.86 0 top
R8015  10KR2J-3-GP  [R402H16]  209.28 70.94 270 top
R9301  0R0402-PAD-2-GP  [0R0402-PAD-1]  42.3 66.99 180 top
R9302  0R0402-PAD-2-GP  [0R0402-PAD-1]  59.26 71.96 180 top
R9304  0R0402-PAD-2-GP  [0R0402-PAD-1]  87.05 70.87 180 top
R9901  0R2J-2-GP  [R402H16]  57.7 85.86 90 top
R9902  1KR2J-1-GP  [R402H16]  49.99 70.36 180 top
R9903  1KR2J-1-GP  [R402H16]  51.08 71.42 180 top
R9904  1KR2J-1-GP  [R402H16]  48.98 70.36 180 top
R9905  2K2R2J-2-GP  [R402H16]  53.89 86.69 0 top
R9906  1KR2J-1-GP  [R402H16]  47.9 90.33 90 top
R9907  0R2J-2-GP  [R402H16]  45.28 91.19 180 top
R9908  0R2J-2-GP  [R402H16]  47.89 91.38 90 top
R9909  0R2J-2-GP  [R402H16]  48.81 85.93 180 top
R9910  0R2J-2-GP  [R402H16]  46.41 91.16 180 top
R9912  10KR2J-3-GP  [R402H16]  50.15 63.73 90 top
R9913  150R2F-1-GP  [R402H16]  53.66 90.63 180 top
R9914  0R2J-2-GP  [R402H16]  45.19 89.22 0 top
R9915  1KR2J-1-GP  [R402H16]  53.75 93.12 90 top
R9916  0R2J-2-GP  [R402H16]  44.11 89.23 0 top
R9917  0R2J-2-GP  [R402H16]  49.15 94.29 180 top
R9918  2K2R2J-2-GP  [R402H16]  48.65 96.3 270 top
R9919  1KR2J-1-GP  [R402H16]  50.17 94.28 180 top
R9920  0R2J-2-GP  [R402H16]  57.2 88.07 180 top
R9921  0R2J-2-GP  [R402H16]  56.13 88.09 180 top
R31132  20KR2J-L2-GP  [R402H16]  199.59 26.54 90 top
R64013  130R5J-GP  [R805H24]  231.53 8.77 0 top
R64014  10KR2J-3-GP  [R402H16]  232.36 32.87 90 top
RN7901  SRN10KJ-11-GP-U  [SMD-ARES4-2H18-U]  220.49 48.73 180 top
RN7902  SRN10KJ-11-GP-U  [SMD-ARES4-2H18-U]  209.36 65.97 90 top
RN7905  SRN10KJ-11-GP-U  [SMD-ARES4-2H18-U]  222.34 48.73 180 top
RN7909  SRN10KJ-11-GP-U  [SMD-ARES4-2H18-U]  217.76 75.67 90 top
RT2402  NTC-10K-19-GP-U  [NTC-402H22-U]  75.06 150.05 0 top
RT2403  NTC-10K-19-GP-U  [NTC-402H22-U]  235.75 156.27 90 top
SATA2  SKT-SATA7P-56-GP  [ABA-SAT-054-K02]  227 38 90 top
SATA3  SKT-SATA7P-56-GP  [ABA-SAT-054-K02]  227 22 90 top
SATA4  SKT-SATA7P-10-GP  [T12-0047-1A30-0]  217 37.76 90 top
SATA5  SKT-SATA7P-10-GP  [T12-0047-1A30-0]  217 19.76 90 top
SATAEX1  SKT-SATA14P-4P-1-GP  [ASAT0008-P001C01]  227 22 90 top
SIO1  IT8732F-CX-GP  [PQFP128H134]  226.35 63.52 0 top
SPI1  SKT-SPI8P-GP-U1  [SKT-SOIC8-092117H235]  182 25 90 top
SPK1  BAOT-CONN8A-SFP-GP-U  [P125-2204P-A1BS-025-U]  38.68 6.5 0 top
TC5  ST47U6D3VBM-3GP  [CT3528H48]  238.36 205.97 180 top
TC2601  E220U16VM-25-GP  [ECAP-100D6D3H473]  229.84 230.12 90 top
TC2602  E220U16VM-25-GP  [ECAP-100D6D3H473]  230.83 139.42 90 top
TC2903  E100U16VM-57-GP-U  [ECAP-100D5H573]  27.06 24.47 0 top
TC2904  E100U16VM-57-GP-U  [ECAP-100D5H573]  20.33 24.47 0 top
TC2924  SC10U6D3V3MX-GP  [C603H38]  18.86 18.34 0 top
TC2925  SC10U6D3V3MX-GP  [C603H38]  17.46 18.34 0 top
TC3001  E100U16VM-57-GP-U  [ECAP-100D5H573]  21.79 38.03 0 top
TC3002  SC10U6D3V3MX-GP  [C603H38]  14.23 56.02 180 top
TC3003  SC10U6D3V3MX-GP  [C603H38]  12.85 55.42 180 top
TC3004  E100U16VM-57-GP-U  [ECAP-100D5H573]  21.78 31.34 0 top
TC3005  SC10U6D3V3MX-GP  [C603H38]  16.57 55.11 180 top
TC3006  SC10U6D3V3MX-GP  [C603H38]  15.4 55.49 180 top
TC3401  E220U16VM-25-GP  [ECAP-100D6D3H473]  134.24 15.62 90 top
TC3601  E220U16VM-25-GP  [ECAP-100D6D3H473]  23.98 136.09 0 top
TC3701  E220U16VM-25-GP  [ECAP-100D6D3H473]  114.47 13.46 90 top
TC3702  E220U16VM-25-GP  [ECAP-100D6D3H473]  102.58 13.5 90 top
TC3801  E220U16VM-25-GP  [ECAP-100D6D3H473]  20.07 178.82 0 top
TC3802  E220U16VM-25-GP  [ECAP-100D6D3H473]  21.97 157.45 0 top
TC3901  E220U16VM-25-GP  [ECAP-100D6D3H473]  126.49 13.97 90 top
TC5002  E820U2D5VM-8-GP  [ECAP-100D6D3H355]  214.27 153.39 0 top
TC5003  E820U2D5VM-8-GP  [ECAP-100D6D3H355]  222.2 153.52 0 top
TC5301  E820U2D5VM-8-GP  [ECAP-100D6D3H355]  106.86 112.78 0 top
TC9302  E220U16VM-25-GP  [ECAP-100D6D3H473]  34.12 74.46 0 top
TC9401  E220U16VM-25-GP  [ECAP-100D6D3H473]  48 27.48 0 top
TC9402  E220U16VM-25-GP  [ECAP-100D6D3H473]  40 29 0 top
TP168  TPAD28-1-GP-U  [TPAD28-1-U]  221.46 52.81 0 top
TP_3G16_JTAG5  -  [TPAD24]  53.58 73.54 0 top
TP_3G16_RSVD_A1  -  [TPAD24]  77.72 86.06 0 top
TP_3G16_RSVD_A2  -  [TPAD24]  76.89 87.2 0 top
TP_3G16_RSVD_A3  -  [TPAD24]  97.92 87.55 0 top
TP_3G16RSVD_A1  -  [TPAD24]  63.31 86.17 0 top
TP_3G18_RSVD_B1  -  [TPAD24]  76.33 86.09 0 top
TP_16PRSNT_B1  -  [TPAD24]  132.89 78 180 bottom
TP_CPU1  -  [TPAD24]  130.79 172.22 180 bottom
TP_CPU2  -  [TPAD24]  130.69 170.44 180 bottom
TP_CPU3  -  [TPAD24]  124.31 180.49 270 bottom
TP_CPU4  -  [TPAD24]  112.86 178.45 180 bottom
TP_CPU7  -  [TPAD24]  111.59 180.58 270 bottom
TP_CPU9  -  [TPAD24]  111.49 179.2 180 bottom
TP_CPU10  -  [TPAD24]  132.07 165.37 270 bottom
TP_CPU11  -  [TPAD24]  132.06 167.82 180 bottom
TP_CPU12  -  [TPAD24]  132.05 166.58 270 bottom
TP_CPU13  -  [TPAD24]  124.13 181.81 180 bottom
TP_CPU_AB37  -  [TPAD28]  125.37 178.64 180 bottom
TP_CPU_AC37  -  [TPAD28]  126.09 179.88 180 bottom
TP_CPU_AC38  -  [TPAD28]  125.5 181.48 180 bottom
TP_CPU_AC40  -  [TPAD24]  123.8 183.49 180 bottom
TP_CPU_AV1  -  [TPAD24]  139.45 145.06 270 bottom
TP_CPU_AV39  -  [TPAD24]  141.04 181.65 270 bottom
TP_CPU_AW2  -  [TPAD24]  140.51 146.05 270 bottom
TP_CPU_AW38  -  [TPAD24]  142.57 182.35 270 bottom
TP_CPU_D14  -  [TPAD28]  109.1 153.92 270 bottom
TP_CPU_G14  -  [TPAD24]  113.29 158.14 270 bottom
TP_CPU_H11  -  [TPAD24]  111.75 153.7 0 bottom
TP_CPU_H12  -  [TPAD24]  113.25 154.76 180 bottom
TP_CPU_H14  -  [TPAD24]  112.49 156.75 270 bottom
TP_CPU_J7  -  [TPAD24]  112.29 151.64 0 bottom
TP_CPU_J8  -  [TPAD24]  114.98 152.44 0 bottom
TP_CPU_K8  -  [TPAD24]  116.36 150.93 0 bottom
TP_CPU_K12  -  [TPAD24]  113.78 156.73 0 bottom
TP_CPU_L8  -  [TPAD24]  115.12 151.03 0 bottom
TP_CPU_L12  -  [TPAD24]  115.87 155.05 180 bottom
TP_DIMM_12V  -  [TPAD24]  187.32 235.69 180 bottom
TP_DIMM_12V1  -  [TPAD24]  198.98 235.97 90 bottom
TP_DIMM_12V2  -  [TPAD24]  179.17 235.66 90 bottom
TP_DIMM_12V3  -  [TPAD24]  206.88 235.66 90 bottom
TP_DIMM_12V4  -  [TPAD24]  180.57 235.69 180 bottom
TP_DIMM_12V5  -  [TPAD24]  200.56 235.94 180 bottom
TP_DIMM_12V6  -  [TPAD24]  175.92 235.08 180 bottom
TP_DIMM_12V7  -  [TPAD24]  192.02 236.09 180 bottom
TP_LAN_PIN25  -  [TPAD28]  31.82 101.25 270 top
TP_LAN_PIN26  -  [TPAD28]  29.63 98.27 270 top
TP_LAN_PIN27  -  [TPAD28]  28.3 91.57 270 top
TP_PCH_AB13  -  [TPAD24]  147.56 49.66 180 bottom
TP_PCH_AN17  -  [TPAD24]  149.36 43.25 180 bottom
TP_PCH_AN29  -  [TPAD24]  155.58 42.37 180 bottom
TP_PCH_AN43  -  [TPAD28]  166.3 42.51 0 top
TP_PCH_AN44  -  [TPAD28]  166.33 43.76 0 top
TP_PCH_AR17  -  [TPAD24]  150.47 42.39 180 bottom
TP_PCH_AR19  -  [TPAD24]  151.54 43 180 bottom
TP_PCH_AR22  -  [TPAD24]  152.99 42.56 180 bottom
TP_PCH_AR39  -  [TPAD28]  159.44 41.61 180 bottom
TP_PCH_AR45  -  [TPAD28]  166.38 41.29 0 top
TP_PCH_AW42  -  [TPAD24]  161.97 40.37 180 bottom
TP_PCH_AW45  -  [TPAD24]  162.97 38.71 180 bottom
TP_PCH_BC1  -  [TPAD28]  149.8 33.59 0 top
TP_PCH_BD14  -  [TPAD24]  148.51 33.76 0 top
TP_PCH_N29  -  [TPAD24]  156.42 53.08 180 bottom
TP_PCH_N31  -  [TPAD24]  157.98 53.23 180 bottom
TP_PCH_N45  -  [TPAD24]  147.31 37.71 180 bottom
TP_PCH_P24  -  [TPAD24]  151.56 52.22 180 bottom
TP_PCH_P27  -  [TPAD24]  154.32 52.3 180 bottom
TP_PCH_P29  -  [TPAD24]  158.32 51.81 180 bottom
TP_PCH_P31  -  [TPAD24]  157.11 51.57 180 bottom
TP_PCH_R24  -  [TPAD24]  152.9 51.84 180 bottom
TP_PCH_R27  -  [TPAD24]  155.32 51.56 180 bottom
TP_PCH_U13  -  [TPAD24]  146.76 51.17 180 bottom
TP_PCH_W13  -  [TPAD24]  146.34 49.73 180 bottom
TP_SET1  -  [TPAD24]  76.92 216.58 0 top
TP_SET2  -  [TPAD24]  78.25 216.39 0 top
TP_SET3  -  [TPAD24]  77.82 218.4 0 top
TP_SET4  -  [TPAD24]  66.24 224.13 0 top
TP_SET5  -  [TPAD24]  68.04 228.65 0 top
TP_SET6  -  [TPAD24]  62.51 223.71 0 top
TP_SET7  -  [TPAD24]  78.88 217.38 0 top
TP_SET8  -  [TPAD24]  77.48 221.47 0 top
TP_SLP_S5  -  [TPAD28]  146.78 39.04 180 bottom
TP_SUS_WARNB  -  [TPAD28]  154.83 27.29 0 top
TP_SUSACK_N  -  [TPAD28]  156.29 28.41 0 top
TP_VBAT_1  -  [TPAD28]  99.99 18.63 270 top
TP_VBAT_2  -  [TPAD28]  99.99 17.36 270 top
TR5701  FILTER-4P-99-GP  [L125100-4PH24]  20.24 186.28 90 top
TR5702  FILTER-4P-99-GP  [L125100-4PH24]  20.24 188.44 90 top
TR5703  FILTER-4P-99-GP  [L125100-4PH24]  20.24 190.6 90 top
TR5704  FILTER-4P-99-GP  [L125100-4PH24]  20.24 192.76 90 top
U2  MBT3904DW1T1G-2-GP  [SOT-363H44]  214.39 209.93 90 top
U2RJ1  SKT-RJ45-USB-38-GP  [RU1-AQ1K9WGF]  19.43 122 270 top
U5  2N7002KDW-1-GP  [SOT-363H44]  236.09 218.44 270 top
U16  APL1085UC-GP  [SMD-TO-252-4H94]  236.55 191.28 0 top
U25  2N7002KDW-1-GP  [SOT-363H44]  233.38 213.21 0 top
U26  2N7002KDW-1-GP  [SOT-363H44]  236.44 213.21 0 top
U27  2N7002KDW-1-GP  [SOT-363H44]  214.58 214.38 180 top
U28  2N7002KDW-1-GP  [SOT-363H44]  210.52 213.77 180 top
U62  SNLVC1G08DCKRG4-GP  [SC70-5H44]  218.44 216.79 0 top
U63  SNLVC1G08DCKRG4-GP  [SC70-5H44]  223.52 216.92 0 top
U401  ME2N7002E-G-GP  [SOT23DGS2D4H44]  122.65 32.9 270 top
U402  ME2N7002E-G-GP  [SOT23DGS2D4H44]  118.96 32.83 180 top
U403  ME2N7002E-G-GP  [SOT23DGS2D4H44]  118.93 36.51 270 top
U404  ME2N7002E-G-GP  [SOT23DGS2D4H44]  180.95 10.9 180 top
U2501  MX25L6473EM21-10G-GP  [SOIC8-1H86]  182 25 270 top
U2701  ALC662-VD-GR-GP  [LQFP48H63]  17.16 48.23 270 top
U3101  RTL8111GA-CG-GP-U  [QFN32J4-G2D85H36]  25.76 84.82 90 top
U3102  ME2N7002E-G-GP  [SOT23DGS2D4H44]  35.39 86 180 top
U3401  TPS2540ARTER-GP  [QFN16-G1D8-UH32]  74.98 28.54 90 top
U3402  P5003QVG-1-GP  [SOIC8H79]  73.8 40.35 180 top
U3601  GS7605ST-R-GP  [SOT23-8PH36]  11.48 134.26 270 top
U3602  AZC099-04S-R7G-GP  [SOT-6H58]  29.87 109.47 90 top
U3603  GS7605ST-R-GP  [SOT23-8PH36]  96.67 15.21 180 top
U3604  GS7605ST-R-GP  [SOT23-8PH36]  92.08 12.82 180 top
U3605  SY6288CAAC-GP  [SOT-23-5H56]  8.56 156.87 90 top
U3606  SY6288CAAC-GP  [SOT-23-5H56]  7.09 180.21 90 top
U3607  GS7605ST-R-GP  [SOT23-8PH36]  155.58 14.79 180 top
U3608  SY6288CAAC-GP  [SOT-23-5H56]  116.66 7.21 180 top
U3701  AZC099-04S-R7G-GP  [SOT-6H58]  108.56 15.49 180 top
U3702  AZC099-04S-R7G-GP  [SOT-6H58]  87.86 15.52 180 top
U3801  AZ1045-04F-R7G-GP  [DFN10G2510H26]  19.43 142.16 270 top
U3802  AZ1045-04F-R7G-GP  [DFN10G2510H26]  18.8 150.98 270 top
U3803  AZC099-04S-R7G-GP  [SOT-6H58]  19.79 146.63 270 top
U3804  AZC099-04S-R7G-GP  [SOT-6H58]  19.56 168.02 270 top
U3805  AZ1045-04F-R7G-GP  [DFN10G2510H26]  19.2 163.55 270 top
U3806  AZ1045-04F-R7G-GP  [DFN10G2510H26]  18.57 172.36 270 top
U3901  AZ1045-04F-R7G-GP  [DFN10G2510H26]  140.08 14.73 180 top
U3902  AZ1045-04F-R7G-GP  [DFN10G2510H26]  144.83 14.76 180 top
U3903  AZC099-04S-R7G-GP  [SOT-6H58]  149.79 15.75 0 top
U4002  SLG7NT4375VTR-1-GP  [QFN12J1D6H24]  235.8 223.41 0 top
U5202  2N7002A-7-GP  [SOT23DGS2D4H48]  53.18 98.04 270 top
U5203  2N7002A-7-GP  [SOT23DGS2D4H48]  58.16 99.19 0 top
U7902  MX25L1006EMI-10G-GP  [SOIC8H69]  204.67 74.02 270 top
USB2F2  JWT-CONN10D-SFP10-GP  [A2541WV0-2AX5PA-6T-K]  107 6.5 0 top
USB3F1  LOTES-CONN20C-SFP1-GP  [ABA-USB-050-K07]  144 7.5 0 top
USB3R1  SKT-USB22-13-GP  [SKT-USB22-156174]  8.64 168 270 top
USB3R2  SKT-USB22-13-GP  [SKT-USB22-156174]  8.64 145 270 top
WP1  PIN-CON3-S-GP  [21S-91-03GB01]  176 7.63 270 top
WPWR1  JWT-CON2-S14-GP  [A2008WV0-2P]  123 7.26 0 top
X1801  XTAL-32D768KHZ-64-GP  [SMD49-6914-0403H56]  146.18 26.81 270 top
X1802  XTAL-24MHZ-126-GP  [OSC-3225-4P-4H36]  134.92 59.94 90 top
X3101  XTAL-25MHZ-181-GP  [OSC-3225-4P-4H36]  26.49 95.53 180 top
XDP1  DM-SMC-CONN60A-GP-01  [DM-BSH-03001-FDA-01]  51 95 180 bottom

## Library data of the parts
ATX1 = C4201WV0-B2X12P: tolerance: 21.70163.212
ATX2 = C4201WV0-2-2P: tolerance: 20.80991.004
AUDF1 = 1E450400: tolerance: 21.62868.205
AUDR1 = ABA-JAK-028-K03: tolerance: 22.10251.831
BT1 = AAA-BAT-029-K01: tolerance: 22.70034.011
BUZ1 = HY-11H394: tolerance: 23.60004.051
C2 C3 C11-C13 C371 C372 C447 C475 C476 C726 C1103 C1109-C1113 C1122 C1130-C1132 C1135 C1137 C1138 C1140 C1141 C1143-C1146 C1202 C1203 C1208 C1212-C1217 C1219 C1220 C1305-C1309 C1311 C1312 C1314 C1315 C1407-C1411 C1413 C1414 C1416 C1417 C2002 C2007 C2008 C2101 C2308-C2322 C2504 C2603 C2605 C2713 C2721 C2723 C2726-C2728 C2731 C2734-C2736 C2920 C2921 C3103-C3107 C3109-C3112 C3114 C3141-C3143 C3204 C3205 C3207 C3401-C3403 C3605 C3606 C3702-C3705 C3714 C3802 C3804 C3805 C3807 C3902 C3903 C4302 C4304-C4306 C5609-C5611 C5713 C6403-C6405 C9321 C9322 C9329 C9330 C9404-C9412 C9415 C9902 PC5007 PC5106 PC5111 PC5206 = C402H22: tolerance: 78.10421.2FL
C5 C6 C9 C1204 C1205 C2503 C2717-C2720 C4307-C4311 C9310-C9312 C9402 C9403 C9413 C9414 PC4703 PC4706 PC4710 PC4734 PC4802 PC4806 PC5005 PC5105 PC5205 = C603H36: tolerance: 78.10422.2BL
C364 C2729 C2730 C2732 C2733 C3803 C3806 = C805H54: tolerance: 78.10623.51L
C365 C2038 C3113 C3121 C7906 C7908 C7909 C7911-C7916 C7919-C7921 C7925 C7927 C15159 = C402H22: tolerance: 78.10491.4FL
C367 = C805H54: tolerance: 78.47593.41L
C420-C422 C1049 C2001 C2003 C2004 C2006 C2301 PC4635 PC5002 PC5003 PC5109 = C402H22: tolerance: 78.10520.5FL
C467-C474 = C402H22: tolerance: 78.22423.5FL; signal model: 2pins
C707 C773 C774 PC5041 = C402H22: tolerance: 78.10421.2FLDL
C708 C727 C775 PC5035 PC5040 = C402H22: tolerance: 78.10523.5FLDL
C728 C729 PC5033 PC5034 = C805H50: tolerance: 78.10623.51LDL
C1004-C1009 C1014-C1020 C1025-C1028 C1030-C1034 C1043-C1048 C1050-C1053 C1091-C1093 C1095-C1098 C1129 C2302-C2307 C2722 C7905 C7917 = C805H58: tolerance: 78.22610.51L
C1037-C1042 C1070-C1075 C1084-C1089 C1099 C1100 C1124-C1128 = C603H40: tolerance: 78.22610.5BL
C1054-C1069 C1077 C1079 C1081 = C805H54: tolerance: 78.47610.51L
C1101 C1106-C1108 C1201 C1209-C1211 C1301-C1304 C1401 C1404-C1406 C2501 C2912 C2918 C2919 C3809-C3813 C6402 C6406 C7901 C7902 C7907 PC5202 PC5203 = C402H22: tolerance: 78.10523.5FL
C1102 C1207 C1310 C1412 C3508 = C603H36: tolerance: 78.47520.5BL
C1123 C1133 C1136 C1139 C1142 C1218 C1313 C1415 = C402H22: tolerance: 78.22523.5FL
C1134 C1206 = C402H22: tolerance: 78.22321.2FL
C1601 C1604 C1606 C1607 C1617 C1618 C9302-C9309 C9313-C9320 C9323-C9328 C9331-C9340 = C402H22: tolerance: 78.22421.2FL; signal model: 2pins
C1602 C1603 C1605 C1608 C5601-C5608 C5702-C5711 EC3801-EC3808 EC3901-EC3904 = C402H22: tolerance: 78.10421.2FL; signal model: 2pins
C1701 = C402H22: tolerance: 78.47034.1FL
C1801 C1804 = C402H22: tolerance: 78.4R074.1FL
C1802 C1803 = C402H22: tolerance: 78.8R074.1FL
C2601 C2604 C3115 C7903 PC5307 = C603H36: tolerance: 78.10521.5BL
C2602 = C805H58: tolerance: 78.10522.21L
C2712 = C402H22: tolerance: 78.22034.1FL
C2724 C2725 = C805H54: tolerance: 78.10693.41L
C2932 C3201 C3206 C3601 C3701 C3706 C3715 C3801 C3901 C6401 PC4705 PC4709 PC4713 PC4737 PC4804 PC4810 PC5011 PC5108 PC5308 = C402H22: tolerance: 78.10224.2FL
C2934-C2937 C3001-C3006 C7904 PC5208 = C402H22: tolerance: 78.10134.1FL
C3101 C3116 = C402H22: tolerance: 78.15034.1FL
C3102 C3108 C3123 C3124 C3140 = C603H36: tolerance: 78.47523.5BL
C3202 PC4605 PC4606 PC4628 PC4633 PC4634 PC4646 PC4701 PC4716 PC4717 PC4735 PC4803 PC4807 PC5020 = C402H22: tolerance: 78.10324.2FL
C3504 C3506 C3507 C3509-C3511 = C603H36: tolerance: 78.10593.4BL
C3708-C3710 C3904 = C1206H71: tolerance: 78.22611.52L
C4301 C4303 C5612 C5613 C5701 C5712 PC4602 PC4631 = C402H22: tolerance: 78.47124.2FL
C6002-C6017 = C402H22: tolerance: 78.10324.2FL; signal model: 2pins
C6110 C6112 C6113 PC5211 PC5304-PC5306 = C402H22: tolerance: 78.10422.2FL
C6111 = C805H54: tolerance: 78.10620.51L
C6214 = C603H36: tolerance: 78.10424.2BL
C7918 PC4632 = C402H22: tolerance: 78.22510.5FL
C9420 C9422 = C402H22: tolerance: 78.10034.1FL
C15160 C15161 PC4655 PC4704 PC4708 PC4712 PC4805 PC4809 PC5438 = C402H22: tolerance: 78.10521.5FL
CMOS1 MECLR1 WP1 = 21S-91-03GB01: tolerance: 21.61445.103
CPU1 = SKTBGA1151R754612-UH369: tolerance: 062.10015.0081
CRF1 = 210-91-05GY21-U: tolerance: 21.62967.105
D4 = SOD323AKH42: tolerance: 83.R3004.A8F
D20 D21 D2906 D2907 = SOT23-2D4-312H48: tolerance: 75.00054.R7D
D2502 = SOT-23-9H44: tolerance: 75.00040.07D
D2601 D5601 = SOD323AKH38: tolerance: 83.00355.D1F
D2602 D2603 = SOD323AKH40: tolerance: 83.00355.F1F
D2702 = D1608AK-UH28: tolerance: 75.0DF2B.077
D3001 D3004 D3006 = SOD-523-4H28: tolerance: 75.05125.070
D3002 D3003 D3005 = SOT23-2D4-312H46: tolerance: 075.05125.007D
DBGH1 = 220-47-07GB22: tolerance: 21.62888.207
DIMM1-DIMM4 = AH08847-A9L2-4M: tolerance: 022.10010.0761
DP1 = 105020-0001: tolerance: 22.10329.161
ED3201 ED3203 ED3204 U3602 U3701 U3702 U3803 U3804 U3903 = SOT-6H58: tolerance: 075.09904.007C
ED5601-ED5603 ED5701 ED5702 U3801 U3802 U3805 U3806 U3901 U3902 = DFN10G2510H26: tolerance: 75.01045.073
ED5703 = DFN10G2510H26: tolerance: 75.01045.073; signal model: 10pins2
EL3201-EL3204 EL3802 EL3805 EL3807 EL3808 = L125100-4P-1H37: tolerance: 68.01012.201; signal model: 4pins1
EL3603-EL3605 EL3701-EL3703 EL3904 EL3905 = L125100-4P-4H28: tolerance: 068.01012.2011; signal model: 4pins1
EL3801 EL3803 EL3804 EL3806 EL3809-EL3812 EL3901-EL3903 EL3906 = L125100-4P-5H24: tolerance: 68.24500.201; signal model: L125100-4P-5H24_FILTER-4P-98-GP
EL5601-EL5604 = L125100-4PH26: tolerance: 068.12102.2001; signal model: 4pins2
EL6001-EL6008 = L125100-4PH26: tolerance: 68.00242.031; signal model: 4pins2
F5601 F5602 = POLYSW-3217-UH40: tolerance: 69.50007.D21
FANC1 FANS1 FANS3 = HF1004E: tolerance: 21.60626.104
FANS2 = A2543WV2-3P: tolerance: 20.60333.103
FL2906-FL2909 R2102 R2104 R2105 R2108 R2109 R2129 R2301-R2304 R2406 R2609 R2621 R2701 R2705-R2707 = 0R0603-PAD-1-U: tolerance: ZZ.00PAD.M21
G7901 PG4701-PG4706 PG4801-PG4804 PG5201-PG5204 = CON2C-U: tolerance: ZZ.CON2C.XXX
GPIO1 GPIO2 JP1 = A2541WV0-1EX2PA-6T: tolerance: 21.60909.102
H1-H8 = GENS315R158-8-F-A: tolerance: ZZ.SCREW.541
HDMI1 = SKT-HDMI23-150122-10: tolerance: 62.10078.B31
HS1 = STF256R109H99: tolerance: 34.3NH01.001
HS2 HS3 = STF256R113-UH258: tolerance: 34.3HJ03.001
L2702 = L20125H44: tolerance: 68.00206.121
L2901 = L20125H44: tolerance: 68.00206.051
L3001-L3006 L6401 = L603H38: tolerance: 68.00335.091
L3101 = L35301330H103: tolerance: 68.4R710.20H
L5601 L7901 = L603H38: tolerance: 68.00335.081
L6801 = L1608-UH38: tolerance: 68.00217.351
LEDH1 = T11-0063-1A40-0-U: tolerance: 21.62738.207
LEDH2 = 210-92-07GB11: tolerance: 21.62924.207
NGFFE1 = AS0BC21-S40BE-7H: tolerance: 062.10003.0611
NGFFM1 = AS0BC21-S85BM-7H: tolerance: 062.10003.0601
PC301 = C402H22: tolerance: 78.18224.2FL
PC4610 PC4630 = C402H22: tolerance: 78.68034.1FL
PC4636 PC4637 = C402H22: tolerance: 78.22421.2FL
PC4639-PC4644 = C402H22: tolerance: 78.18134.1FL
PC4645 PC4720-PC4723 PC4812 PC4813 = C402H22: tolerance: 78.47423.5FL
PC4666 PC5219 = C402H22: tolerance: 78.10424.5FL
PC4702 PC4707 PC4711 PC4736 PC4801 PC4808 PC5004 PC5102 PC5103 PC5204 PC5427 = C1206H71: tolerance: 78.10622.52L
PC5006 = C603H36: tolerance: 78.10613.5BL
PC5009 PC5101 TC2924 TC2925 TC3002 TC3003 TC3005 TC3006 = C603H38: tolerance: 78.10610.5BL
PC5010 = C603H36: tolerance: 78.10610.5BLLL
PC5012 = C402H22: tolerance: 78.33321.2FL
PC5013 PC5110 = C402H22: tolerance: 78.22034.1FLLL
PC5036 PC5037 = C805H54: tolerance: 78.22610.51LDL
PC5038 = C402H22: tolerance: 78.3R374.1FLDL
PC5039 = C402H22: tolerance: 78.68124.2FLDL
PC5201 = C603: tolerance: 78.22224.2BL
PC5207 PC5210 = C402H22: tolerance: 78.22322.2FL
PC5209 = C402H22: tolerance: 78.10234.1FL
PC5268 = C402H22: tolerance: 78.47134.1FL
PC5301-PC5303 PC5310 = C805H56: tolerance: 78.10622.51L
PC5309 = C402H22: tolerance: 78.18034.1FL
PC5311 = C402H22: tolerance: 78.10520.5FLLL
PCH1 = BGA837M23-1H58: tolerance: 071.SUNRI.0A0U
PCIE1 PCIE2 = AAA-PCI-003-K45: tolerance: 20.50394.036
PCIE16 = 4-1470780-7: tolerance: 20.50232.164
PD5001 PD5002 PD5101 PD5102 = D5126145AKH91: tolerance: 83.3R004.Y8M
PG4699 = GAP-OPEN-PWR-2: tolerance: ZZ.00PAD.BE1
PG5001 PG5101 = GAP-CLOSE-PWR-3: tolerance: ZZ.CLOSE.001
PL12 PL5101 = L686647-127318H119: tolerance: 68.1R51A.10F
PL4701-PL4704 = L112100-2135H158: tolerance: 068.R3610.1011
PL4801 PL4802 = RT-D6-4D5-1010H375: tolerance: 19.40335.121
PL5001 = RT-D6D2-108108H426: tolerance: 019.40022.0011
PL5203 = L686647-127318H119: tolerance: 68.R681A.10A
PL5301 = L686647-127318H119: tolerance: 68.2R21B.10J
PN4603-PN4606 = NTC-402H24-U: tolerance: 69.60013.201
PR302 PR4662 PR4668 PR4702 PR4703 PR4706-PR4708 PR4711 PR4713 PR4714 PR4718 PR4752 PR4755 PR4801 PR4804 PR4811-PR4813 PR4817 PR5002 PR5010 PR5011 PR5106 PR5107 PR5112 PR5202 PR5203 PR5206 PR5305 PR5306 PR5309 PR5311 PR5456 = R805H24: tolerance: 63.2R231.16L
PR977 PR4633 PR4659 PR4692 PR5001 PR5210 PR5301 PR5320 PR5413 PR5458 R74 R76 R85 R402 R406 R695 R696 R699 R802 R919 R920 R982-R984 R1125 R1201 R1520 R1703 R1801 R2007 R2014 R2057 R2060 R2067 R2107 R2110 R2480 R2601 R2604 R2628 R2921 R2922 R2934 R2936 R3101 R3107 R3108 R3815 R3918 R3920 R4025 R4202 R4203 R4305 R6106 R6107 R6109 R6209 R6211-R6213 R6215 R7925 R7929 R7954 R7974-R7976 R9301 R9302 R9304 = 0R0402-PAD-1: tolerance: ZZ.00PAD.M11
PR4601 PR4682 R1610 R5601 = R402H16: tolerance: 64.10035.6DL
PR4602 = R402H16: tolerance: 64.39015.6DL
PR4603 = R402H16: tolerance: 64.30025.6DL
PR4604 PR4720-PR4725 PR4802 PR4803 PR4805-PR4807 PR5013 PR5016 PR5017 PR5019-PR5027 PR5101-PR5103 PR5114-PR5117 PR5205 PR5217-PR5219 PR5302 PR5303 PR5313-PR5315 PR5321 R3164 = 0R0805-PAD-1-U: tolerance: ZZ.00PAD.M31
PR4611 PR4621-PR4623 PR4639 PR4652 PR4727 PR4729 PR4731 PR4733 PR4821 PR4823 R3109 = R402H16: tolerance: 64.68005.6DL
PR4616 PR4635 R471 R2613 R2634 = R402H14: tolerance: 63.10134.1DL
PR4629 = R402H16: tolerance: 64.28005.6DL
PR4630 PR5316 = R402H16: tolerance: 64.33025.6DL
PR4632 = R402H16: tolerance: 64.10225.6DL
PR4640 = R402H16: tolerance: 64.60425.6DL
PR4641 = R402H16: tolerance: 64.32R45.6DL
PR4642 = R402H16: tolerance: 64.16025.6DL
PR4643 = R402H16: tolerance: 64.13015.6DL
PR4644 = R402H16: tolerance: 64.68025.6DL
PR4645 = R402H16: tolerance: 64.22615.6DL
PR4646 = R402H16: tolerance: 64.16525.6DL
PR4647 = R402H16: tolerance: 64.30905.6DL
PR4648 R449 = R402H16: tolerance: 64.63415.6DL
PR4649 R902 = R402H16: tolerance: 64.20R05.6DL
PR4650 = R402H16: tolerance: 64.33215.6DL
PR4651 = R402H16: tolerance: 64.16935.6DL
PR4653 = R402H16: tolerance: 64.91005.6DL
PR4654 = R402H16: tolerance: 64.18725.6DL
PR4655 = R402H16: tolerance: 64.27405.6DL
PR4656 R448 = R402H16: tolerance: 64.28015.6DL
PR4657 = R402H16: tolerance: 64.12025.6DL
PR4658 = R402H16: tolerance: 64.32415.6DL
PR4660 = R402H14: tolerance: 64.82R05.6DL
PR4661 = R402H16: tolerance: 64.43035.6DL
PR4663 = R805H24: tolerance: 64.49935.16L
PR4664 = R402H16: tolerance: 63.1R034.1DL
PR4665 PR4671 PR4694 PR5113 PR5144 PR5212 R63 R65 R155 R1502 R1504-R1506 R2509 R3001 R3502 R3525 R3526 R4606 R7946 R7953 R7959 R7964 R7969 R7997 R7998 = R402H16: tolerance: 64.10025.6DL
PR4666 = R402H16: tolerance: 64.30915.6DL
PR4667 PR5146 = R402H16: tolerance: 64.18025.6DL
PR4669 = R402H16: tolerance: 64.12425.6DL
PR4670 R415 = R402H16: tolerance: 64.49R95.6DL
PR4672 PR4676 PR5145 = R402H16: tolerance: 64.51025.6DL
PR4673 PR4675 = R603H22: tolerance: 64.30035.55L
PR4674 PR4677 = R402H16: tolerance: 64.86615.6DL
PR4678 PR4681 R421 = R402H16: tolerance: 64.75R05.6DL
PR4679 = R402H16: tolerance: 64.45R35.6DL
PR4680 PR4685 PR4688 PR5214-PR5216 PR5310 R389 R467 R1608 R2607 = R402H14: tolerance: 64.10005.6DL
PR4683 = R402H16: tolerance: 64.12735.6DL
PR4684 = R402H16: tolerance: 64.51035.6DL
PR4686 = R402H16: tolerance: 64.43025.6DL
PR4687 = R402H16: tolerance: 64.16535.6DL
PR4689 PR5318 PR5319 R804 R805 R921-R926 = 0R0402-PAD-1: tolerance: ZZ.00PAD.M11; signal model: 2pins
PR4690 = R402H16: tolerance: 64.10525.6DL
PR4691 = R402H14: tolerance: 64.10R05.6DL
PR4693 PR4695 R73 R452 R454-R456 R472 R473 R532 R533 R652 R653 R806 R807 R811 R985-R990 R1701 R1708-R1711 R2012 R2036 R2101 R2476-R2478 R2512 R2908 R3104 R3110 R3112 R3401 R3408-R3411 R3418 R4010 R4011 R4014-R4017 R4019 R4021-R4024 R4026 R6102-R6104 R6114-R6118 R6210 R7977 R9901 R9907-R9910 R9914 R9916 R9917 R9920 R9921 = R402H16: tolerance: 63.R0034.1DL
PR4704 PR4709 PR4715 PR4741-PR4748 PR4808 PR4814 PR4825-PR4828 PR5104 PR5108 PR5204 PR5304 PR5453 R64 R79 R84 R91-R99 R243 R244 R474 R476-R479 R655 R866 R884 R991 R1532 R1534-R1536 R1601 R1615-R1622 R1809-R1812 R1814 R1815 R1901 R1902 R1905 R1907 R1908 R2011 R2023 R2026 R2027 R2032 R2034 R2045 R2047 R2066 R2201 R2225 R2608 R2614 R2625 R2629 R2708 R2711 R2715 R2931 R2935 R3160 R3162 R3165-R3167 R3402 R3403 R3405-R3407 R3416 R3522 R3524 R3527 R3601 R3701 R3703 R3705 R3813 R3814 R3821 R3822 R3914 R3916 R4306 R4311 R4693 R5201 R5205 R5704 R6105 R6110 R6403 R6405 R6409 R6411 R6419 R6801 R7961 R8000 R8001 R8013-R8015 R9912 R64014 = R402H16: tolerance: 63.10334.1DL
PR4705 PR4712 PR4717 PR4754 PR4810 PR4816 = R1206H28: tolerance: 63.2R232.11L
PR4726 PR4728 PR4730 PR4732 = R402H16: tolerance: 64.97605.6DL
PR4820 PR4822 = R402H16: tolerance: 64.12015.6DL
PR5003 = R402H16: tolerance: 64.11525.6DL
PR5008 = R402H16: tolerance: 64.62035.6DL
PR5009 PR5105 R62 R77 R81 R82 R523-R525 R530 R888 R2031 R2615 R2627 R3159 R3516 R3521 R5701 R5706 R5712 R5714 R7938 = R402H16: tolerance: 63.10434.1DL
PR5012 PR5111 = R805H24: tolerance: 64.2R205.16L
PR5015 R979 R980 R2606 = R402H16: tolerance: 64.82015.6DL
PR5018 = R402H16: tolerance: 64.13325.6DL
PR5109 PR5201 PR5207 = R402H16: tolerance: 64.49925.6DL
PR5110 = R402H16: tolerance: 64.47035.6DL
PR5118 R4303 = R402H16: tolerance: 64.22025.6DL
PR5142 = R402H16: tolerance: 64.5R105.6DL
PR5143 = R402H16: tolerance: 64.16235.6DL
PR5208 = R805H24: tolerance: 63.1R031.16L
PR5209 = R402H16: tolerance: 64.69815.6DL
PR5211 = R402H16: tolerance: 64.95315.6DL
PR5213 = R402H16: tolerance: 64.30015.6DL; signal model: 2pins
PR5307 = R402H16: tolerance: 64.34025.6DL
PR5308 = R402H16: tolerance: 64.47035.6DL; signal model: 2pins
PR5312 = R402H16: tolerance: 64.11825.6DL; signal model: 2pins
PR5317 = R402H14: tolerance: 64.10005.6DL; signal model: 2pins
PT1 PT2 PT4701 PT4703-PT4706 PT4801 PT4803-PT4806 PT5107 PT5202-PT5204 TC5002 TC5003 TC5301 = ECAP-100D6D3H355: tolerance: 09.8271N.09L
